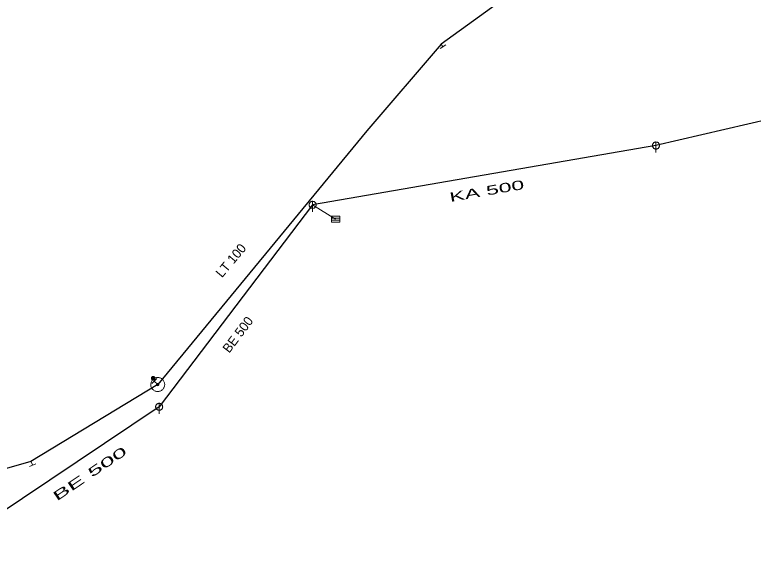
# Model space of a CAD drawing. Extents: x -687468 to -685917, y -974192 to -973456.
# Drawn here: x -686788.4 to -686735.6, y -973728.6 to -973689.6 of the extents above; entities that cross this region are included whole.
import ezdxf
from ezdxf.enums import TextEntityAlignment as Align

# ---------------------------------------------------------------- set-up
doc = ezdxf.new("R2010")
doc.units = 0
doc.header["$LTSCALE"] = 0.27
for name, color, linetype, lineweight in [('1', 7, 'Continuous', 13), ('11', 7, 'Continuous', 13), ('14', 7, 'Continuous', 25), ('17', 7, 'Continuous', 25), ('22', 7, 'Continuous', 13), ('34', 7, 'Continuous', 13), ('47', 7, 'Continuous', 13), ('9', 7, 'Continuous', 13)]:
    doc.layers.add(name, color=color, linetype=linetype, lineweight=lineweight)

msp = doc.modelspace()

# ---------------------------------------------------------------- linework, layer by layer
at = {"layer": '11'}
msp.add_line((-686765.44, -973704.18), (-686767.08, -973703.16), dxfattribs=at)
at = {"layer": '14'}
for p, q in [((-686704.809, -973690.17), (-686742.511, -973698.919)), ((-686742.511, -973698.919), (-686767.08, -973703.16)), ((-686767.079, -973703.16), (-686778.059, -973717.6))]:
    msp.add_line(p, q, dxfattribs=at)
at = {"layer": '14', "lineweight": 13}
for p, q in [((-686757.875, -973691.668), (-686757.75, -973691.859)), ((-686778.409, -973715.759), (-686778.489, -973715.559)), ((-686778.16, -973716.008), (-686778.409, -973715.759)), ((-686787.234, -973721.504), (-686787.109, -973721.78))]:
    msp.add_line(p, q, dxfattribs=at)
at = {"layer": '14'}
msp.add_lwpolyline([(-686778.059, -973717.6), (-686789.822, -973725.456), (-686796.46, -973725.17)], dxfattribs=at)
at = {"layer": '17'}
for points in [[(-686737.661, -973680.49), (-686749.647, -973685.721), (-686757.875, -973691.668), (-686763.192, -973697.859), (-686778.16, -973716.008)], [(-686778.16, -973716.008), (-686787.234, -973721.504), (-686796.6, -973724.188), (-686817.64, -973721.881), (-686819.859, -973721.829), (-686837.05, -973722.085), (-686859.074, -973725.682), (-686861.337, -973725.804), (-686883.709, -973728.57)]]:
    msp.add_lwpolyline(points, dxfattribs=at)
at = {"layer": '22'}
for p, q in [((-686742.51, -973698.667), (-686742.511, -973699.411)), ((-686767.078, -973702.908), (-686767.079, -973703.652)), ((-686765.735, -973704.109), (-686765.137, -973704.109)), ((-686765.735, -973704.255), (-686765.137, -973704.255)), ((-686778.058, -973717.348), (-686778.059, -973718.092))]:
    msp.add_line(p, q, dxfattribs=at)
for points in [[(-686742.259, -973698.919), (-686742.26, -973698.893), (-686742.264, -973698.867), (-686742.27, -973698.841), (-686742.28, -973698.817), (-686742.292, -973698.793), (-686742.306, -973698.771), (-686742.323, -973698.75), (-686742.341, -973698.732), (-686742.362, -973698.715), (-686742.384, -973698.701), (-686742.408, -973698.689), (-686742.432, -973698.679), (-686742.458, -973698.673), (-686742.484, -973698.669), (-686742.51, -973698.667), (-686742.536, -973698.668), (-686742.562, -973698.672), (-686742.588, -973698.678), (-686742.613, -973698.688), (-686742.636, -973698.7), (-686742.658, -973698.714), (-686742.679, -973698.731), (-686742.697, -973698.749), (-686742.714, -973698.77), (-686742.728, -973698.792), (-686742.74, -973698.816), (-686742.75, -973698.84), (-686742.757, -973698.866), (-686742.761, -973698.892), (-686742.763, -973698.918), (-686742.762, -973698.944), (-686742.758, -973698.97), (-686742.751, -973698.996), (-686742.741, -973699.021), (-686742.729, -973699.044), (-686742.715, -973699.066), (-686742.698, -973699.087), (-686742.68, -973699.105), (-686742.659, -973699.122), (-686742.637, -973699.136), (-686742.614, -973699.148), (-686742.589, -973699.158), (-686742.563, -973699.165), (-686742.537, -973699.169), (-686742.511, -973699.171), (-686742.485, -973699.17), (-686742.459, -973699.166), (-686742.433, -973699.159), (-686742.409, -973699.149), (-686742.385, -973699.137), (-686742.363, -973699.123), (-686742.342, -973699.106), (-686742.324, -973699.088), (-686742.307, -973699.067), (-686742.293, -973699.045), (-686742.281, -973699.022), (-686742.271, -973698.997), (-686742.265, -973698.971), (-686742.261, -973698.945)], [(-686766.827, -973703.16), (-686766.828, -973703.134), (-686766.832, -973703.108), (-686766.838, -973703.082), (-686766.848, -973703.058), (-686766.86, -973703.034), (-686766.874, -973703.012), (-686766.891, -973702.991), (-686766.909, -973702.973), (-686766.93, -973702.956), (-686766.952, -973702.942), (-686766.976, -973702.93), (-686767, -973702.92), (-686767.026, -973702.914), (-686767.052, -973702.91), (-686767.078, -973702.908), (-686767.104, -973702.909), (-686767.13, -973702.913), (-686767.156, -973702.919), (-686767.181, -973702.929), (-686767.204, -973702.941), (-686767.226, -973702.955), (-686767.247, -973702.972), (-686767.265, -973702.99), (-686767.282, -973703.011), (-686767.296, -973703.033), (-686767.308, -973703.057), (-686767.318, -973703.081), (-686767.325, -973703.107), (-686767.329, -973703.133), (-686767.331, -973703.159), (-686767.33, -973703.185), (-686767.326, -973703.211), (-686767.319, -973703.237), (-686767.309, -973703.262), (-686767.297, -973703.285), (-686767.283, -973703.307), (-686767.266, -973703.328), (-686767.248, -973703.346), (-686767.227, -973703.363), (-686767.205, -973703.377), (-686767.182, -973703.389), (-686767.157, -973703.399), (-686767.131, -973703.406), (-686767.105, -973703.41), (-686767.079, -973703.412), (-686767.053, -973703.411), (-686767.027, -973703.407), (-686767.001, -973703.4), (-686766.977, -973703.39), (-686766.953, -973703.378), (-686766.931, -973703.364), (-686766.91, -973703.347), (-686766.892, -973703.329), (-686766.875, -973703.308), (-686766.861, -973703.286), (-686766.849, -973703.263), (-686766.839, -973703.238), (-686766.833, -973703.212), (-686766.829, -973703.186)], [(-686765.735, -973703.963), (-686765.137, -973703.963), (-686765.137, -973704.4), (-686765.735, -973704.4)], [(-686777.807, -973717.6), (-686777.808, -973717.574), (-686777.812, -973717.548), (-686777.818, -973717.522), (-686777.828, -973717.498), (-686777.84, -973717.474), (-686777.854, -973717.452), (-686777.871, -973717.431), (-686777.889, -973717.413), (-686777.91, -973717.396), (-686777.932, -973717.382), (-686777.956, -973717.37), (-686777.98, -973717.36), (-686778.006, -973717.354), (-686778.032, -973717.35), (-686778.058, -973717.348), (-686778.084, -973717.349), (-686778.11, -973717.353), (-686778.136, -973717.359), (-686778.161, -973717.369), (-686778.184, -973717.381), (-686778.206, -973717.395), (-686778.227, -973717.412), (-686778.245, -973717.43), (-686778.262, -973717.451), (-686778.276, -973717.473), (-686778.288, -973717.497), (-686778.298, -973717.521), (-686778.305, -973717.547), (-686778.309, -973717.573), (-686778.311, -973717.599), (-686778.31, -973717.625), (-686778.306, -973717.651), (-686778.299, -973717.677), (-686778.289, -973717.702), (-686778.277, -973717.725), (-686778.263, -973717.747), (-686778.246, -973717.768), (-686778.228, -973717.786), (-686778.207, -973717.803), (-686778.185, -973717.817), (-686778.162, -973717.829), (-686778.137, -973717.839), (-686778.111, -973717.846), (-686778.085, -973717.85), (-686778.059, -973717.852), (-686778.033, -973717.851), (-686778.007, -973717.847), (-686777.981, -973717.84), (-686777.957, -973717.83), (-686777.933, -973717.818), (-686777.911, -973717.804), (-686777.89, -973717.787), (-686777.872, -973717.769), (-686777.855, -973717.748), (-686777.841, -973717.726), (-686777.829, -973717.703), (-686777.819, -973717.678), (-686777.813, -973717.652), (-686777.809, -973717.626)]]:
    msp.add_lwpolyline(points, close=True, dxfattribs=at)
at = {"layer": '34'}
for p, q in [((-686757.957, -973691.994), (-686757.542, -973691.723)), ((-686778.584, -973715.934), (-686778.233, -973715.583)), ((-686787.335, -973721.881), (-686786.882, -973721.678))]:
    msp.add_line(p, q, dxfattribs=at)
at = {"layer": '47'}
for points in [[(-686777.845, -973715.619), (-686777.887, -973715.588), (-686777.933, -973715.562), (-686777.98, -973715.541), (-686778.03, -973715.525), (-686778.081, -973715.514), (-686778.134, -973715.509), (-686778.186, -973715.509), (-686778.238, -973715.514), (-686778.289, -973715.525), (-686778.339, -973715.541), (-686778.387, -973715.562), (-686778.432, -973715.589), (-686778.474, -973715.619), (-686778.513, -973715.654), (-686778.548, -973715.693), (-686778.579, -973715.735), (-686778.605, -973715.781), (-686778.626, -973715.829), (-686778.642, -973715.878), (-686778.653, -973715.929), (-686778.658, -973715.982), (-686778.659, -973716.035), (-686778.653, -973716.087), (-686778.643, -973716.137), (-686778.626, -973716.187), (-686778.605, -973716.235), (-686778.579, -973716.281), (-686778.548, -973716.322), (-686778.513, -973716.361), (-686778.474, -973716.396), (-686778.432, -973716.427), (-686778.386, -973716.453), (-686778.338, -973716.475), (-686778.289, -973716.49), (-686778.238, -973716.501), (-686778.186, -973716.507), (-686778.133, -973716.507), (-686778.081, -973716.502), (-686778.03, -973716.491), (-686777.98, -973716.474), (-686777.932, -973716.453), (-686777.887, -973716.427), (-686777.845, -973716.396), (-686777.806, -973716.361), (-686777.771, -973716.322), (-686777.74, -973716.28), (-686777.714, -973716.234), (-686777.693, -973716.187), (-686777.677, -973716.137), (-686777.666, -973716.086), (-686777.66, -973716.034), (-686777.66, -973715.982), (-686777.666, -973715.93), (-686777.677, -973715.878), (-686777.693, -973715.828), (-686777.714, -973715.78), (-686777.74, -973715.736), (-686777.771, -973715.693), (-686777.806, -973715.654)], [(-686778.108, -973715.944), (-686778.115, -973715.938), (-686778.122, -973715.935), (-686778.13, -973715.931), (-686778.138, -973715.928), (-686778.147, -973715.927), (-686778.155, -973715.926), (-686778.164, -973715.925), (-686778.172, -973715.926), (-686778.181, -973715.929), (-686778.189, -973715.931), (-686778.197, -973715.935), (-686778.204, -973715.939), (-686778.211, -973715.944), (-686778.218, -973715.949), (-686778.223, -973715.956), (-686778.229, -973715.963), (-686778.232, -973715.97), (-686778.236, -973715.978), (-686778.239, -973715.986), (-686778.24, -973715.995), (-686778.241, -973716.003), (-686778.242, -973716.012), (-686778.241, -973716.02), (-686778.239, -973716.029), (-686778.236, -973716.037), (-686778.232, -973716.045), (-686778.228, -973716.052), (-686778.223, -973716.059), (-686778.218, -973716.066), (-686778.211, -973716.071), (-686778.204, -973716.077), (-686778.197, -973716.08), (-686778.189, -973716.084), (-686778.181, -973716.087), (-686778.172, -973716.088), (-686778.164, -973716.09), (-686778.155, -973716.09), (-686778.147, -973716.089), (-686778.138, -973716.087), (-686778.13, -973716.084), (-686778.122, -973716.08), (-686778.115, -973716.076), (-686778.108, -973716.071), (-686778.101, -973716.066), (-686778.096, -973716.059), (-686778.09, -973716.052), (-686778.087, -973716.045), (-686778.083, -973716.037), (-686778.08, -973716.029), (-686778.079, -973716.02), (-686778.077, -973716.012), (-686778.077, -973716.003), (-686778.078, -973715.995), (-686778.081, -973715.986), (-686778.083, -973715.978), (-686778.087, -973715.97), (-686778.091, -973715.963), (-686778.096, -973715.956), (-686778.101, -973715.949)]]:
    msp.add_lwpolyline(points, close=True, dxfattribs=at)
at = {"layer": '9'}
for points in [[(-686778.362, -973715.559), (-686778.364, -973715.546), (-686778.365, -973715.533), (-686778.369, -973715.52), (-686778.374, -973715.508), (-686778.379, -973715.496), (-686778.387, -973715.485), (-686778.394, -973715.475), (-686778.404, -973715.465), (-686778.414, -973715.457), (-686778.426, -973715.45), (-686778.438, -973715.444), (-686778.45, -973715.439), (-686778.463, -973715.436), (-686778.475, -973715.434), (-686778.489, -973715.433), (-686778.502, -973715.434), (-686778.514, -973715.436), (-686778.527, -973715.439), (-686778.539, -973715.444), (-686778.551, -973715.45), (-686778.563, -973715.457), (-686778.573, -973715.465), (-686778.583, -973715.475), (-686778.59, -973715.485), (-686778.598, -973715.496), (-686778.603, -973715.508), (-686778.608, -973715.52), (-686778.612, -973715.533), (-686778.614, -973715.546), (-686778.615, -973715.559), (-686778.614, -973715.572), (-686778.612, -973715.585), (-686778.608, -973715.598), (-686778.603, -973715.61), (-686778.598, -973715.622), (-686778.59, -973715.633), (-686778.583, -973715.643), (-686778.573, -973715.653), (-686778.563, -973715.661), (-686778.551, -973715.668), (-686778.539, -973715.674), (-686778.527, -973715.679), (-686778.514, -973715.682), (-686778.502, -973715.684), (-686778.489, -973715.685), (-686778.475, -973715.684), (-686778.463, -973715.682), (-686778.45, -973715.679), (-686778.438, -973715.674), (-686778.426, -973715.668), (-686778.414, -973715.661), (-686778.404, -973715.653), (-686778.394, -973715.643), (-686778.387, -973715.633), (-686778.379, -973715.622), (-686778.374, -973715.61), (-686778.369, -973715.598), (-686778.365, -973715.585), (-686778.364, -973715.572)], [(-686778.382, -973715.559), (-686778.382, -973715.548), (-686778.384, -973715.537), (-686778.387, -973715.526), (-686778.392, -973715.516), (-686778.397, -973715.506), (-686778.402, -973715.497), (-686778.409, -973715.488), (-686778.418, -973715.48), (-686778.426, -973715.473), (-686778.436, -973715.467), (-686778.446, -973715.462), (-686778.455, -973715.458), (-686778.467, -973715.455), (-686778.477, -973715.453), (-686778.489, -973715.453), (-686778.5, -973715.453), (-686778.511, -973715.455), (-686778.522, -973715.458), (-686778.531, -973715.462), (-686778.541, -973715.467), (-686778.551, -973715.473), (-686778.559, -973715.48), (-686778.568, -973715.488), (-686778.575, -973715.497), (-686778.58, -973715.506), (-686778.585, -973715.516), (-686778.59, -973715.526), (-686778.593, -973715.537), (-686778.595, -973715.548), (-686778.595, -973715.559), (-686778.595, -973715.57), (-686778.593, -973715.581), (-686778.59, -973715.592), (-686778.585, -973715.602), (-686778.58, -973715.612), (-686778.575, -973715.621), (-686778.568, -973715.63), (-686778.559, -973715.638), (-686778.551, -973715.645), (-686778.541, -973715.651), (-686778.531, -973715.656), (-686778.522, -973715.66), (-686778.511, -973715.663), (-686778.5, -973715.665), (-686778.489, -973715.665), (-686778.477, -973715.665), (-686778.467, -973715.663), (-686778.455, -973715.66), (-686778.446, -973715.656), (-686778.436, -973715.651), (-686778.426, -973715.645), (-686778.418, -973715.638), (-686778.409, -973715.63), (-686778.402, -973715.621), (-686778.397, -973715.612), (-686778.392, -973715.602), (-686778.387, -973715.592), (-686778.384, -973715.581), (-686778.382, -973715.57)], [(-686778.401, -973715.559), (-686778.402, -973715.55), (-686778.404, -973715.541), (-686778.406, -973715.532), (-686778.409, -973715.524), (-686778.414, -973715.516), (-686778.419, -973715.508), (-686778.424, -973715.501), (-686778.431, -973715.495), (-686778.438, -973715.489), (-686778.446, -973715.484), (-686778.453, -973715.48), (-686778.462, -973715.477), (-686778.47, -973715.474), (-686778.48, -973715.473), (-686778.489, -973715.472), (-686778.497, -973715.473), (-686778.507, -973715.474), (-686778.516, -973715.477), (-686778.524, -973715.48), (-686778.531, -973715.484), (-686778.539, -973715.489), (-686778.546, -973715.495), (-686778.553, -973715.501), (-686778.558, -973715.508), (-686778.563, -973715.516), (-686778.568, -973715.524), (-686778.571, -973715.532), (-686778.573, -973715.541), (-686778.575, -973715.55), (-686778.576, -973715.559), (-686778.575, -973715.568), (-686778.573, -973715.577), (-686778.571, -973715.586), (-686778.568, -973715.594), (-686778.563, -973715.602), (-686778.558, -973715.61), (-686778.553, -973715.617), (-686778.546, -973715.623), (-686778.539, -973715.629), (-686778.531, -973715.634), (-686778.524, -973715.638), (-686778.516, -973715.641), (-686778.507, -973715.644), (-686778.497, -973715.645), (-686778.489, -973715.646), (-686778.48, -973715.645), (-686778.47, -973715.644), (-686778.462, -973715.641), (-686778.453, -973715.638), (-686778.446, -973715.634), (-686778.438, -973715.629), (-686778.431, -973715.623), (-686778.424, -973715.617), (-686778.419, -973715.61), (-686778.414, -973715.602), (-686778.409, -973715.594), (-686778.406, -973715.586), (-686778.404, -973715.577), (-686778.402, -973715.568)], [(-686778.421, -973715.559), (-686778.421, -973715.552), (-686778.424, -973715.545), (-686778.424, -973715.538), (-686778.428, -973715.532), (-686778.431, -973715.526), (-686778.434, -973715.52), (-686778.438, -973715.514), (-686778.443, -973715.509), (-686778.45, -973715.505), (-686778.455, -973715.501), (-686778.462, -973715.498), (-686778.468, -973715.495), (-686778.475, -973715.494), (-686778.482, -973715.492), (-686778.489, -973715.492), (-686778.495, -973715.492), (-686778.502, -973715.494), (-686778.509, -973715.495), (-686778.516, -973715.498), (-686778.522, -973715.501), (-686778.527, -973715.505), (-686778.534, -973715.509), (-686778.539, -973715.514), (-686778.543, -973715.52), (-686778.546, -973715.526), (-686778.549, -973715.532), (-686778.553, -973715.538), (-686778.554, -973715.545), (-686778.556, -973715.552), (-686778.556, -973715.559), (-686778.556, -973715.566), (-686778.554, -973715.573), (-686778.553, -973715.58), (-686778.549, -973715.586), (-686778.546, -973715.593), (-686778.543, -973715.598), (-686778.539, -973715.604), (-686778.534, -973715.609), (-686778.527, -973715.613), (-686778.522, -973715.617), (-686778.516, -973715.62), (-686778.509, -973715.623), (-686778.502, -973715.625), (-686778.495, -973715.626), (-686778.489, -973715.626), (-686778.482, -973715.626), (-686778.475, -973715.625), (-686778.468, -973715.623), (-686778.462, -973715.62), (-686778.455, -973715.617), (-686778.45, -973715.613), (-686778.443, -973715.609), (-686778.438, -973715.604), (-686778.434, -973715.598), (-686778.431, -973715.593), (-686778.428, -973715.586), (-686778.424, -973715.58), (-686778.424, -973715.573), (-686778.421, -973715.566)], [(-686778.441, -973715.559), (-686778.441, -973715.554), (-686778.443, -973715.549), (-686778.443, -973715.544), (-686778.446, -973715.54), (-686778.448, -973715.535), (-686778.451, -973715.531), (-686778.453, -973715.528), (-686778.458, -973715.524), (-686778.46, -973715.521), (-686778.465, -973715.518), (-686778.47, -973715.516), (-686778.473, -973715.514), (-686778.478, -973715.513), (-686778.483, -973715.512), (-686778.489, -973715.512), (-686778.494, -973715.512), (-686778.499, -973715.513), (-686778.504, -973715.514), (-686778.507, -973715.516), (-686778.512, -973715.518), (-686778.517, -973715.521), (-686778.521, -973715.524), (-686778.524, -973715.528), (-686778.526, -973715.531), (-686778.529, -973715.535), (-686778.531, -973715.54), (-686778.534, -973715.544), (-686778.534, -973715.549), (-686778.536, -973715.554), (-686778.536, -973715.559), (-686778.536, -973715.564), (-686778.534, -973715.569), (-686778.534, -973715.574), (-686778.531, -973715.578), (-686778.529, -973715.583), (-686778.526, -973715.587), (-686778.524, -973715.591), (-686778.521, -973715.594), (-686778.517, -973715.597), (-686778.512, -973715.6), (-686778.507, -973715.602), (-686778.504, -973715.604), (-686778.499, -973715.605), (-686778.494, -973715.606), (-686778.489, -973715.606), (-686778.483, -973715.606), (-686778.478, -973715.605), (-686778.473, -973715.604), (-686778.47, -973715.602), (-686778.465, -973715.6), (-686778.46, -973715.597), (-686778.458, -973715.594), (-686778.453, -973715.591), (-686778.451, -973715.587), (-686778.448, -973715.583), (-686778.446, -973715.578), (-686778.443, -973715.574), (-686778.443, -973715.569), (-686778.441, -973715.564)], [(-686778.462, -973715.559), (-686778.462, -973715.556), (-686778.462, -973715.553), (-686778.463, -973715.551), (-686778.463, -973715.548), (-686778.465, -973715.545), (-686778.467, -973715.543), (-686778.468, -973715.541), (-686778.47, -973715.539), (-686778.473, -973715.537), (-686778.475, -973715.535), (-686778.477, -973715.534), (-686778.48, -973715.533), (-686778.482, -973715.532), (-686778.485, -973715.532), (-686778.489, -973715.532), (-686778.492, -973715.532), (-686778.495, -973715.532), (-686778.497, -973715.533), (-686778.5, -973715.534), (-686778.502, -973715.535), (-686778.504, -973715.537), (-686778.507, -973715.539), (-686778.509, -973715.541), (-686778.511, -973715.543), (-686778.512, -973715.545), (-686778.514, -973715.548), (-686778.514, -973715.551), (-686778.516, -973715.553), (-686778.516, -973715.556), (-686778.517, -973715.559), (-686778.516, -973715.562), (-686778.516, -973715.565), (-686778.514, -973715.568), (-686778.514, -973715.57), (-686778.512, -973715.573), (-686778.511, -973715.575), (-686778.509, -973715.578), (-686778.507, -973715.58), (-686778.504, -973715.581), (-686778.502, -973715.583), (-686778.5, -973715.584), (-686778.497, -973715.585), (-686778.495, -973715.586), (-686778.492, -973715.586), (-686778.489, -973715.587), (-686778.485, -973715.586), (-686778.482, -973715.586), (-686778.48, -973715.585), (-686778.477, -973715.584), (-686778.475, -973715.583), (-686778.473, -973715.581), (-686778.47, -973715.58), (-686778.468, -973715.578), (-686778.467, -973715.575), (-686778.465, -973715.573), (-686778.463, -973715.57), (-686778.463, -973715.568), (-686778.462, -973715.565), (-686778.462, -973715.562)], [(-686778.48, -973715.559), (-686778.48, -973715.558), (-686778.48, -973715.557), (-686778.482, -973715.557), (-686778.482, -973715.556), (-686778.482, -973715.555), (-686778.482, -973715.554), (-686778.482, -973715.554), (-686778.483, -973715.553), (-686778.483, -973715.553), (-686778.485, -973715.552), (-686778.485, -973715.552), (-686778.487, -973715.552), (-686778.487, -973715.551), (-686778.487, -973715.551), (-686778.489, -973715.551), (-686778.49, -973715.551), (-686778.49, -973715.551), (-686778.49, -973715.552), (-686778.492, -973715.552), (-686778.492, -973715.552), (-686778.494, -973715.553), (-686778.494, -973715.553), (-686778.495, -973715.554), (-686778.495, -973715.554), (-686778.495, -973715.555), (-686778.495, -973715.556), (-686778.497, -973715.557), (-686778.497, -973715.557), (-686778.497, -973715.558), (-686778.497, -973715.559), (-686778.497, -973715.56), (-686778.497, -973715.561), (-686778.497, -973715.561), (-686778.495, -973715.562), (-686778.495, -973715.563), (-686778.495, -973715.564), (-686778.495, -973715.564), (-686778.494, -973715.565), (-686778.494, -973715.565), (-686778.492, -973715.566), (-686778.492, -973715.566), (-686778.49, -973715.567), (-686778.49, -973715.567), (-686778.49, -973715.567), (-686778.489, -973715.567), (-686778.487, -973715.567), (-686778.487, -973715.567), (-686778.487, -973715.567), (-686778.485, -973715.566), (-686778.485, -973715.566), (-686778.483, -973715.565), (-686778.483, -973715.565), (-686778.482, -973715.564), (-686778.482, -973715.564), (-686778.482, -973715.563), (-686778.482, -973715.562), (-686778.482, -973715.561), (-686778.48, -973715.561), (-686778.48, -973715.56)]]:
    msp.add_lwpolyline(points, close=True, dxfattribs=at)

# ---------------------------------------------------------------- texts
at = {"layer": '1'}
for s, rotation, width, p in [('KA 500', 10, 1.85, (-686754.56, -973702.489)), ('BE 500', 34, 2.1, (-686782.84, -973722.657))]:
    msp.add_text(s, height=0.6667, rotation=rotation, dxfattribs=dict(at, width=width)).set_placement(p, align=Align.CENTER)
for s, rotation, p in [('LT 100', 50, (-686772.672, -973707.352)), ('BE 500', 53, (-686772.165, -973712.638))]:
    msp.add_text(s, height=0.6667, rotation=rotation, dxfattribs=at).set_placement(p, align=Align.CENTER)

doc.saveas('drawing.dxf')
